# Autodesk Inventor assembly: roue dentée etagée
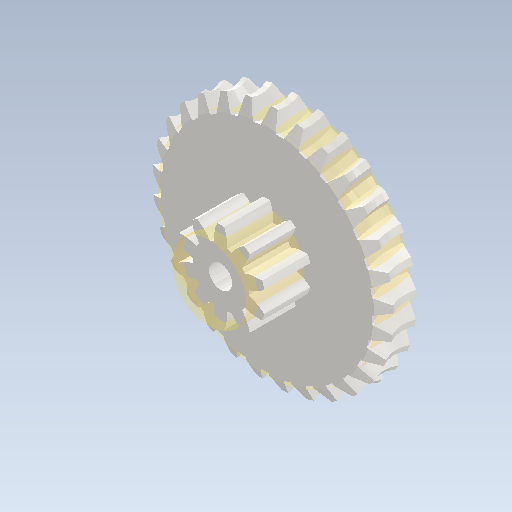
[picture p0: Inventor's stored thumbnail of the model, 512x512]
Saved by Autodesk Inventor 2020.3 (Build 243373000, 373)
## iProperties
Created: 2020-11
Part Number: roue dentée etagée
Document SubType Name: Assembly
Designer: ficho
Mass: 7.89268 g
Surface Area: 12.0168 cm^2
Volume: 1.00544 cm^3
Density: 7.85 g/cm^3
Author: ficho
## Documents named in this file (3)
- D:\travail\année 2020-2021\2I2D\laveur de vitre\Lave vitre\4 Dossier Ressources\1 Modèles 3D Solidworks\adaptation inventor\roue dentée etagée.iam
- D:\travail\année 2020-2021\2I2D\laveur de vitre\Lave vitre\4 Dossier Ressources\1 Modèles 3D Solidworks\adaptation inventor\satellite.ipt
- D:\travail\année 2020-2021\2I2D\laveur de vitre\Lave vitre\4 Dossier Ressources\1 Modèles 3D Solidworks\adaptation inventor\Engrenage à vis sans fin2.ipt
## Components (2 placed, 2 different names)
1. Engrenage cylindrique2:1 — Logement:1
2. Engrenage à vis sans fin:1 — Logement:1
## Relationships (1: Insert 1)
- Logement:1 [Insert]: Engrenage cylindrique2:1 ↔ Engrenage à vis sans fin:1
